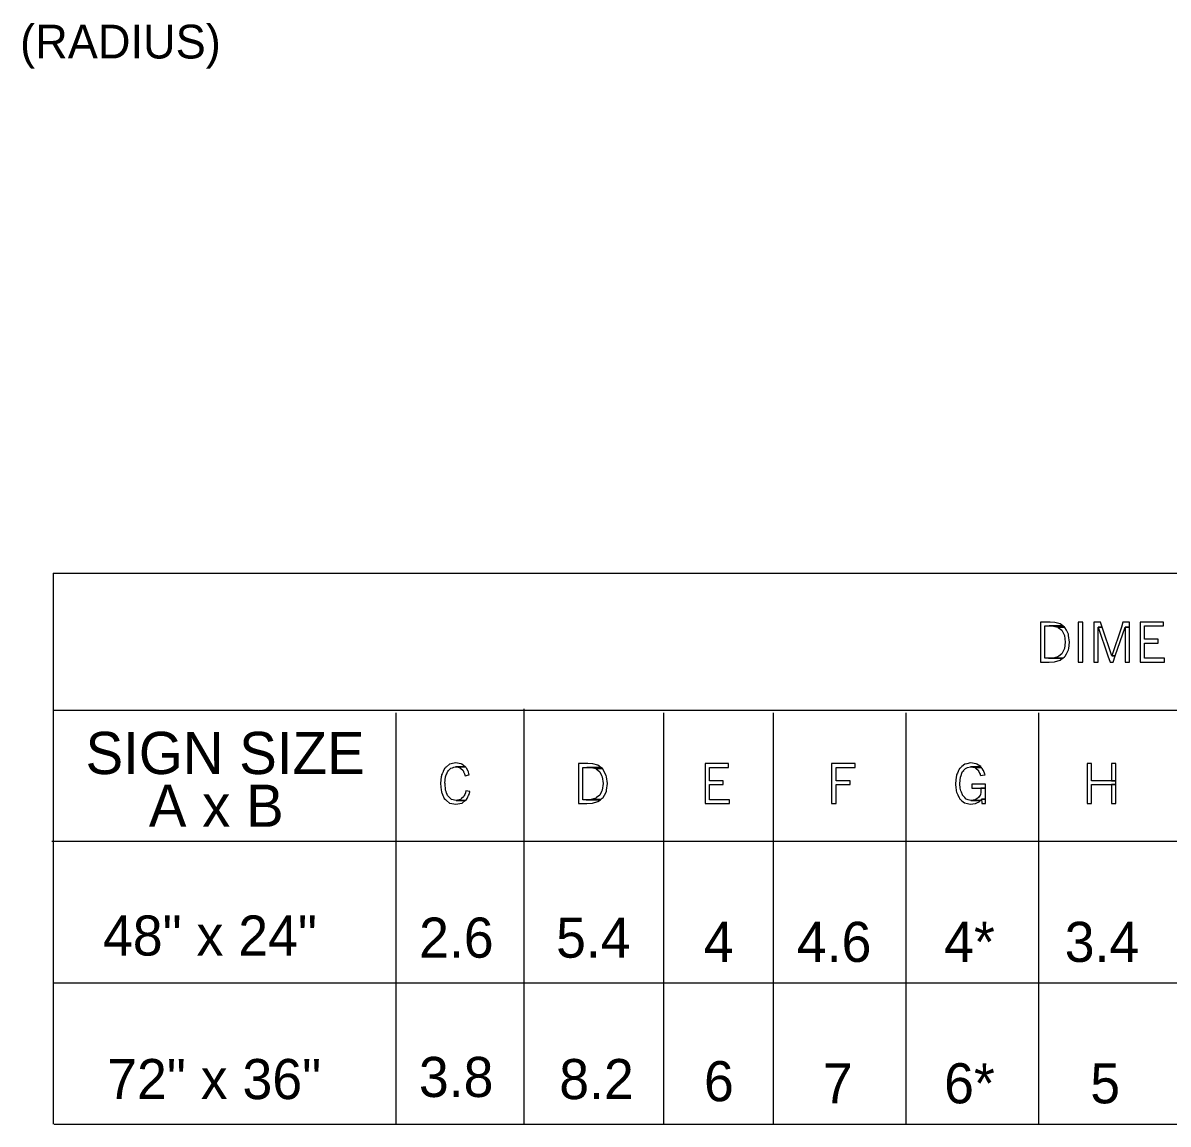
# Model space of a CAD drawing. Extents: x 0.011 to 0.188, y 0.004 to 0.261.
# Drawn here: x 0.0289 to 0.0973, y 0.0538 to 0.1195 of the extents above; entities that cross this region are included whole.
import ezdxf

# ---------------------------------------------------------------- set-up
doc = ezdxf.new("R2010")
doc.units = 0
doc.layers.add('3', color=7, linetype='Continuous')

msp = doc.modelspace()

# ---------------------------------------------------------------- linework, layer by layer
at = {"layer": '3'}
for p, q in [((0.030682, 0.086699), (0.030682, 0.053813)), ((0.030682, 0.086699), (0.184743, 0.086699)), ((0.184743, 0.078509), (0.030682, 0.078509)), ((0.051139, 0.078357), (0.051139, 0.053813)), ((0.058785, 0.078609), (0.058785, 0.053813)), ((0.067132, 0.078357), (0.067132, 0.053813)), ((0.073681, 0.078357), (0.073681, 0.053813)), ((0.081602, 0.078357), (0.081602, 0.053813)), ((0.089513, 0.078357), (0.089513, 0.053813)), ((0.030615, 0.070697), (0.184743, 0.070697)), ((0.030682, 0.062255), (0.184743, 0.062255)), ((0.03075, 0.053813), (0.184743, 0.053813))]:
    msp.add_line(p, q, dxfattribs=at)
for points in [[(0.089642, 0.081406), (0.089642, 0.081386), (0.090151, 0.081386), (0.090481, 0.081406), (0.09081, 0.081506), (0.090958, 0.08162), (0.089902, 0.08162), (0.089902, 0.081634), (0.089902, 0.081706), (0.089902, 0.081745), (0.089902, 0.081893), (0.089902, 0.082116), (0.089902, 0.082197), (0.089902, 0.082578), (0.089902, 0.08258), (0.089902, 0.082981), (0.089902, 0.08306), (0.089902, 0.083288), (0.089902, 0.083456), (0.089902, 0.083473), (0.089902, 0.08354), (0.089902, 0.08355), (0.090973, 0.08355), (0.090806, 0.083677), (0.090494, 0.083759), (0.090209, 0.083773), (0.089642, 0.083773), (0.089642, 0.083759), (0.089642, 0.083677), (0.089642, 0.08355), (0.089642, 0.08354), (0.089642, 0.083473), (0.089642, 0.083456), (0.089642, 0.083288), (0.089642, 0.08306), (0.089642, 0.082981), (0.089642, 0.08258), (0.089642, 0.082578), (0.089642, 0.082197), (0.089642, 0.082116), (0.089642, 0.081893), (0.089642, 0.081745), (0.089642, 0.081706), (0.089642, 0.081634), (0.089642, 0.08162), (0.089642, 0.081506)], [(0.090423, 0.08354), (0.090673, 0.083473), (0.091075, 0.083473), (0.090987, 0.08354), (0.090973, 0.08355), (0.09015, 0.08355)], [(0.090679, 0.081706), (0.090402, 0.081634), (0.090975, 0.081634), (0.091069, 0.081706), (0.091118, 0.081745), (0.091196, 0.081893), (0.091313, 0.082116), (0.091324, 0.082197), (0.091374, 0.082578), (0.091375, 0.08258), (0.091318, 0.082981), (0.091307, 0.08306), (0.091186, 0.083288), (0.091098, 0.083456), (0.091075, 0.083473), (0.090673, 0.083473), (0.090695, 0.083456), (0.090913, 0.083288), (0.091025, 0.08306), (0.091065, 0.082981), (0.091114, 0.08258), (0.091114, 0.082578), (0.091064, 0.082197), (0.091024, 0.082116), (0.090914, 0.081893), (0.090727, 0.081745)], [(0.091895, 0.083773), (0.091895, 0.081386), (0.092162, 0.081386), (0.092162, 0.083773)], [(0.092819, 0.081756), (0.092819, 0.081386), (0.093073, 0.081386), (0.093073, 0.081756), (0.093073, 0.083486), (0.093318, 0.083486), (0.093223, 0.083773), (0.092819, 0.083773), (0.092819, 0.083486)], [(0.093663, 0.081756), (0.09379, 0.081386), (0.09397, 0.081386), (0.094096, 0.081756), (0.09389, 0.081756), (0.093318, 0.083486), (0.093073, 0.083486)], [(0.094466, 0.083486), (0.09389, 0.081756), (0.094096, 0.081756), (0.094687, 0.083486), (0.094941, 0.083486), (0.094941, 0.083773), (0.094561, 0.083773)], [(0.094687, 0.081756), (0.094687, 0.081386), (0.094941, 0.081386), (0.094941, 0.081756), (0.094941, 0.083486), (0.094687, 0.083486)], [(0.095583, 0.081616), (0.095583, 0.081386), (0.097046, 0.081386), (0.097046, 0.081616), (0.095845, 0.081616), (0.095845, 0.082529), (0.096656, 0.082529), (0.096656, 0.08275), (0.095845, 0.08275), (0.095845, 0.083547), (0.09699, 0.083547), (0.09699, 0.083773), (0.095583, 0.083773), (0.095583, 0.083547), (0.095583, 0.08275), (0.095583, 0.082529)], [(0.090402, 0.081634), (0.090113, 0.08162), (0.090958, 0.08162), (0.090975, 0.081634)], [(0.054365, 0.072977), (0.054732, 0.072906), (0.055097, 0.072977), (0.055101, 0.07298), (0.055292, 0.073133), (0.054743, 0.073133), (0.054476, 0.073192), (0.054473, 0.073193), (0.054471, 0.073194), (0.054471, 0.073194), (0.054413, 0.073251), (0.054413, 0.073251), (0.054306, 0.073357), (0.054237, 0.073425), (0.054211, 0.073496), (0.05418, 0.073578), (0.054159, 0.073635), (0.05415, 0.07366), (0.054116, 0.073753), (0.054085, 0.074137), (0.054083, 0.07416), (0.05412, 0.074541), (0.054139, 0.074594), (0.05416, 0.074653), (0.054162, 0.074658), (0.054185, 0.074724), (0.054229, 0.074843), (0.05425, 0.074866), (0.0543, 0.074917), (0.054429, 0.075053), (0.054435, 0.075059), (0.054533, 0.075089), (0.054604, 0.07511), (0.054603, 0.07511), (0.054712, 0.075143), (0.055285, 0.075143), (0.055085, 0.075289), (0.055084, 0.075289), (0.055055, 0.07531), (0.054713, 0.075369), (0.054713, 0.075369), (0.054446, 0.07531), (0.054349, 0.075289), (0.054175, 0.075143), (0.054136, 0.07511), (0.05411, 0.075089), (0.054075, 0.075059), (0.054067, 0.075053), (0.054002, 0.074917), (0.053977, 0.074866), (0.053966, 0.074843), (0.053908, 0.074724), (0.053876, 0.074658), (0.053873, 0.074653), (0.053867, 0.074594), (0.05386, 0.074541), (0.053817, 0.07416), (0.053815, 0.074137), (0.053855, 0.073753), (0.053865, 0.07366), (0.053867, 0.073635), (0.053893, 0.073578), (0.05393, 0.073496), (0.053961, 0.073425), (0.053992, 0.073357), (0.054039, 0.073251), (0.054104, 0.073194), (0.054106, 0.073193), (0.054107, 0.073192), (0.054174, 0.073133), (0.054349, 0.07298)], [(0.062048, 0.072964), (0.062048, 0.072944), (0.062557, 0.072944), (0.062887, 0.072964), (0.063216, 0.073064), (0.063364, 0.073178), (0.062308, 0.073178), (0.062308, 0.073192), (0.062308, 0.073264), (0.062308, 0.073303), (0.062308, 0.073451), (0.062308, 0.073674), (0.062308, 0.073755), (0.062308, 0.074136), (0.062308, 0.074138), (0.062308, 0.074539), (0.062308, 0.074618), (0.062308, 0.074846), (0.062308, 0.075014), (0.062308, 0.075031), (0.062308, 0.075098), (0.062308, 0.075108), (0.063379, 0.075108), (0.063212, 0.075235), (0.0629, 0.075317), (0.062615, 0.075331), (0.062048, 0.075331), (0.062048, 0.075317), (0.062048, 0.075235), (0.062048, 0.075108), (0.062048, 0.075098), (0.062048, 0.075031), (0.062048, 0.075014), (0.062048, 0.074846), (0.062048, 0.074618), (0.062048, 0.074539), (0.062048, 0.074138), (0.062048, 0.074136), (0.062048, 0.073755), (0.062048, 0.073674), (0.062048, 0.073451), (0.062048, 0.073303), (0.062048, 0.073264), (0.062048, 0.073192), (0.062048, 0.073178), (0.062048, 0.073064)], [(0.069608, 0.073174), (0.069608, 0.072944), (0.071071, 0.072944), (0.071071, 0.073174), (0.06987, 0.073174), (0.06987, 0.074087), (0.070682, 0.074087), (0.070682, 0.074308), (0.06987, 0.074308), (0.06987, 0.075105), (0.071015, 0.075105), (0.071015, 0.075331), (0.069608, 0.075331), (0.069608, 0.075105), (0.069608, 0.074308), (0.069608, 0.074087)], [(0.077168, 0.074085), (0.077168, 0.072944), (0.07743, 0.072944), (0.07743, 0.074085), (0.078272, 0.074085), (0.078272, 0.07431), (0.07743, 0.07431), (0.07743, 0.075105), (0.078566, 0.075105), (0.078566, 0.075331), (0.077168, 0.075331), (0.077168, 0.075105), (0.077168, 0.07431)], [(0.085286, 0.072942), (0.085439, 0.072906), (0.085756, 0.072942), (0.08576, 0.072944), (0.085843, 0.072987), (0.085977, 0.073057), (0.086051, 0.073135), (0.085477, 0.073135), (0.085328, 0.073177), (0.085199, 0.073213), (0.08518, 0.073233), (0.085117, 0.073299), (0.084983, 0.073442), (0.084976, 0.073461), (0.084913, 0.07363), (0.084884, 0.073706), (0.084855, 0.073786), (0.084848, 0.073874), (0.084827, 0.074125), (0.084826, 0.074146), (0.08486, 0.074519), (0.084895, 0.074617), (0.084903, 0.07464), (0.084914, 0.07467), (0.084926, 0.074705), (0.084948, 0.074764), (0.08498, 0.074854), (0.085052, 0.074926), (0.085063, 0.074937), (0.085164, 0.075037), (0.085196, 0.075069), (0.085286, 0.075093), (0.085285, 0.075093), (0.085464, 0.07514), (0.086077, 0.07514), (0.08607, 0.07515), (0.085843, 0.075296), (0.085803, 0.075322), (0.085462, 0.075369), (0.085462, 0.075369), (0.085241, 0.075322), (0.085118, 0.075296), (0.08494, 0.07515), (0.084929, 0.07514), (0.084871, 0.075093), (0.084842, 0.075069), (0.084804, 0.075037), (0.084756, 0.074937), (0.084751, 0.074926), (0.084717, 0.074854), (0.084675, 0.074764), (0.084647, 0.074705), (0.08463, 0.07467), (0.084617, 0.07464), (0.084614, 0.074617), (0.084602, 0.074519), (0.084559, 0.074146), (0.084556, 0.074125), (0.084587, 0.073874), (0.084597, 0.073786), (0.084606, 0.073706), (0.084616, 0.07363), (0.084699, 0.073461), (0.084708, 0.073442), (0.084779, 0.073299), (0.084811, 0.073233), (0.084834, 0.073213), (0.084876, 0.073177), (0.084925, 0.073135), (0.085015, 0.073057), (0.085095, 0.072987), (0.085276, 0.072944)], [(0.092414, 0.074078), (0.092414, 0.072944), (0.092674, 0.072944), (0.092674, 0.074078), (0.094132, 0.074078), (0.094132, 0.07431), (0.092674, 0.07431), (0.092674, 0.075331), (0.092414, 0.075331), (0.092414, 0.07431)], [(0.093873, 0.075331), (0.093873, 0.07431), (0.094132, 0.07431), (0.094132, 0.075331)], [(0.055272, 0.074653), (0.055287, 0.074594), (0.055514, 0.074653), (0.055535, 0.074658), (0.055515, 0.074724), (0.055515, 0.074724), (0.05548, 0.074843), (0.055473, 0.074866), (0.055443, 0.074917), (0.055364, 0.075053), (0.055364, 0.075053), (0.05536, 0.075059), (0.055343, 0.075089), (0.05533, 0.07511), (0.055285, 0.075143), (0.054712, 0.075143), (0.054869, 0.07511), (0.054971, 0.075089), (0.055004, 0.075059), (0.055011, 0.075053), (0.055159, 0.074917), (0.055184, 0.074866), (0.055195, 0.074843), (0.055253, 0.074724), (0.05527, 0.074658)], [(0.062829, 0.075098), (0.063079, 0.075031), (0.063481, 0.075031), (0.063393, 0.075098), (0.063379, 0.075108), (0.062556, 0.075108)], [(0.063085, 0.073264), (0.062808, 0.073192), (0.063381, 0.073192), (0.063475, 0.073264), (0.063524, 0.073303), (0.063602, 0.073451), (0.063719, 0.073674), (0.06373, 0.073755), (0.06378, 0.074136), (0.063781, 0.074138), (0.063724, 0.074539), (0.063713, 0.074618), (0.063592, 0.074846), (0.063504, 0.075014), (0.063481, 0.075031), (0.063079, 0.075031), (0.063101, 0.075014), (0.063319, 0.074846), (0.063431, 0.074618), (0.063471, 0.074539), (0.06352, 0.074138), (0.06352, 0.074136), (0.06347, 0.073755), (0.06343, 0.073674), (0.06332, 0.073451), (0.063133, 0.073303)], [(0.085464, 0.07514), (0.085722, 0.075093), (0.086111, 0.075093), (0.086077, 0.07514)], [(0.086051, 0.07464), (0.086058, 0.074617), (0.086176, 0.07464), (0.086175, 0.07464), (0.086328, 0.07467), (0.086317, 0.074705), (0.086299, 0.074764), (0.086259, 0.074854), (0.086228, 0.074926), (0.086223, 0.074937), (0.086151, 0.075037), (0.086128, 0.075069), (0.086111, 0.075093), (0.085722, 0.075093), (0.08575, 0.075069), (0.085788, 0.075037), (0.085907, 0.074937), (0.085921, 0.074926), (0.085957, 0.074854), (0.086002, 0.074764), (0.086032, 0.074705), (0.086042, 0.07467)], [(0.085743, 0.073177), (0.085477, 0.073135), (0.086051, 0.073135), (0.08609, 0.073177), (0.086118, 0.073206), (0.086358, 0.073206), (0.086358, 0.073213), (0.086358, 0.073233), (0.086358, 0.073299), (0.086358, 0.073442), (0.086358, 0.073461), (0.086358, 0.07363), (0.086358, 0.073706), (0.086358, 0.073786), (0.086358, 0.073874), (0.086083, 0.073874), (0.086083, 0.073786), (0.086083, 0.073706), (0.086072, 0.07363), (0.086048, 0.073461), (0.086035, 0.073442), (0.085938, 0.073299), (0.085833, 0.073233), (0.085801, 0.073213), (0.085789, 0.073206)], [(0.085533, 0.074102), (0.085533, 0.073874), (0.086358, 0.073874), (0.086358, 0.074102)], [(0.093873, 0.074078), (0.093873, 0.072944), (0.094132, 0.072944), (0.094132, 0.074078)], [(0.055001, 0.073192), (0.054743, 0.073133), (0.055292, 0.073133), (0.055365, 0.073192), (0.055367, 0.073193), (0.055366, 0.073193), (0.055369, 0.073194), (0.055398, 0.073251), (0.055453, 0.073357), (0.055488, 0.073425), (0.055525, 0.073496), (0.055549, 0.073578), (0.055565, 0.073635), (0.055572, 0.07366), (0.055333, 0.073713), (0.05532, 0.07366), (0.055315, 0.073635), (0.055301, 0.073578), (0.055261, 0.073496), (0.055227, 0.073425), (0.055194, 0.073357), (0.055071, 0.073251), (0.055004, 0.073194), (0.055002, 0.073193)], [(0.062808, 0.073192), (0.062519, 0.073178), (0.063364, 0.073178), (0.063381, 0.073192)], [(0.086128, 0.072987), (0.08613, 0.072944), (0.086358, 0.072944), (0.086358, 0.072987), (0.086358, 0.073057), (0.086358, 0.073135), (0.086358, 0.073177), (0.086358, 0.073206), (0.086118, 0.073206), (0.086119, 0.073177), (0.086121, 0.073135), (0.086125, 0.073057)]]:
    msp.add_lwpolyline(points, close=True, dxfattribs=at)

# ---------------------------------------------------------------- texts
for s, height, p in [('(RADIUS)', 0.0020163, (0.028715, 0.117422)), ('SIGN SIZE', 0.0025197, (0.032621, 0.074708)), ('A x B', 0.0025197, (0.036401, 0.071558)), ('48" x 24"', 0.0023943, (0.033663, 0.063872)), ('2.6', 0.0023943, (0.052538, 0.063746)), ('5.4', 0.0023943, (0.060716, 0.063746)), ('4', 0.002394, (0.069536, 0.063494)), ('4.6', 0.0023943, (0.075092, 0.063494)), ('4*', 0.0023943, (0.083884, 0.063494)), ('3.4', 0.0023943, (0.091082, 0.063494)), ('72" x 36"', 0.0023943, (0.033915, 0.055304)), ('3.8', 0.0023943, (0.052525, 0.05543)), ('8.2', 0.0023943, (0.060905, 0.055304)), ('6', 0.002394, (0.069548, 0.055178)), ('7', 0.002394, (0.07664, 0.055052)), ('6*', 0.0023943, (0.083884, 0.055052)), ('5', 0.002394, (0.092608, 0.055052))]:
    msp.add_text(s, height=height, dxfattribs=at).set_placement(p)

doc.saveas('drawing.dxf')
